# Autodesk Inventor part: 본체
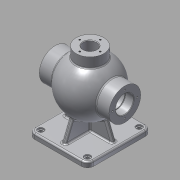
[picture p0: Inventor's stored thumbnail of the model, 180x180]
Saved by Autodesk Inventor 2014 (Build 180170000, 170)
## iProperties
Created: 2015-10
Part Number: 본체
Material: 알루미늄 6061
Document SubType Name: Modeling
Designer: youjin05
Density: 2.71 g/cm^3
Appearance: 알루미늄 - 평지
Mass: 1505.58 g
Surface Area: 1149.71 cm^2
Volume: 555.563 cm^3
Author: youjin05
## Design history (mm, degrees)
sketch "스케치1"
  geometry: L1 (-57.5, -62.5)-(57.5, -62.5); L2 (57.5, -62.5)-(57.5, 62.5); L3 (57.5, 62.5)-(-57.5, 62.5); L4 (-57.5, 62.5)-(-57.5, -62.5); L5 (-57.5, -62.5)-(57.5, 62.5); L6 (57.5, -62.5)-(-57.5, 62.5); 1 further point
  constraints: 12 end point, 2 midpoint, 2 parallel, 1 horizontal, 1 perpendicular
  dimensions: "d0" = 115 distance of L3.end L2.end; "d1" = 125 distance of L2.end L1.end
extrude "돌출1" new body sketch "스케치1" distance "d2" = 10; taper "d3" = 0 deg
sketch "스케치2"
  geometry: L1 (-57.5, 0)-(57.5, 0) reference; L2 (0, 32)-(0, 138); A1 r 53 centre (0, 85) between (0, 32) and (0, 138); 5 further points
  constraints: 3 midpoint, 3 point on circle, 3 vertical alignment, 2 end point, 1 centre point, 1 horizontal alignment, 1 perpendicular
  dimensions: "d6" = 53 radius of A1; "d7" = 85 distance of point (0, 0) A1.centre
revolve "회전1" sketch "스케치2" stored, may be unused: angle "d8" = 90 deg
node "작업 평면1"
sketch "스케치3"
  geometry: C1 r 53 at (0, 85) reference; C2 r 31 at (0, 85); 1 further point
  constraints: 1 centre point, 1 coincident
  dimensions: "d10" = 62 diameter of C2
extrude "돌출2" join sketch "스케치3" distance "d11" = 136; taper "d12" = 0 deg
node "작업 평면2"
sketch "스케치4"
  geometry: C1 r 27 at (0, 0); 1 further point
  constraints: 1 centre point, 1 coincident
  dimensions: "d14" = 54 diameter of C1
extrude "돌출3" join sketch "스케치4" stored distance "d15" = 136; taper "d16" = 0 deg
sketch "스케치5"
  geometry: L1 (-33.719, 44.109)-(-47.5, 10); L2 (-57.5, 0)-(57.5, 0) reference; L3 (57.5, 0)-(57.5, 10) reference; L4 (-57.5, 10)-(57.5, 10) reference; L5 (-57.5, 0)-(-57.5, 10) reference; L6 (-57.5, 10)-(57.5, 10) reference; L7 (-57.5, 0)-(-57.5, 10) reference; L8 (33.719, 44.109)-(47.5, 10); A1 r 53 centre (0, 85) between (-42.988, 54) and (-42.988, 116) reference; 1 further point
  constraints: 4 end point, 2 point on circle, 2 point on line
  dimensions: "d19" = 10 distance of L4.start L1.end; "d20" = 22 deg angle of L5 L1; "d93" = 22 deg angle of L8 L3; "d94" = 10 distance of L3.end L8.end
  node "투영된 루프1"
sketch "스케치6"
  geometry: L1 (-4, -4)-(4, -4); L2 (4, -4)-(4, 4); L3 (4, 4)-(-4, 4); L4 (-4, 4)-(-4, -4); L5 (-4, -4)-(4, 4); L6 (4, -4)-(-4, 4); 1 further point
  constraints: 12 end point, 2 midpoint, 2 parallel, 1 horizontal, 1 perpendicular
  dimensions: "d21" = 8 distance of L3.end L2.end; "d22" = 8 distance of L2.end L1.end
extrude "돌출4" join sketch "스케치6" stored distance "d23" = 136; taper "d24" = 0 deg
sketch "스케치7"
  geometry: L1 (62.5, 10)-(-62.5, 10) reference; L2 (-37.379, 47.426)-(-52.5, 10); L3 (37.379, 47.426)-(52.5, 10); L4 (62.5, 0)-(62.5, 10) reference; L5 (-62.5, 0)-(-62.5, 10) reference; A1 r 53 centre (0, 85) between (-27, 130.607) and (27, 130.607) reference; 1 further point
  constraints: 4 end point, 2 point on circle, 2 point on line
  dimensions: "d27" = 10 distance of L1.start L3.end; "d28" = 22 deg angle of L4 L3; "d29" = 10 distance of L1.end L2.end; "d30" = 22 deg angle of L5 L2
sketch "스케치8"
  geometry: C1 r 27 at (0, 0) reference; 5 further points
  dimensions: "d33" = 91 distance of point (-45.5, 50.5) point (45.5, 50.5); "d34" = 101 distance of point (45.5, 50.5) point (45.5, -50.5); "d35" = 45.5 horizontal distance of point (0, 0) point (45.5, 50.5); "d36" = 50.5 vertical distance of point (0, 0) point (45.5, 50.5); "d37" = 50.5 vertical distance of C1.centre point (-45.5, 50.5); "d38" = 50.5 vertical distance of point (-45.5, -50.5) point (0, 0); "d39" = 91 distance of point (45.5, -50.5) point (-45.5, -50.5); "d40" = 45.5 horizontal distance of point (0, 0) point (-45.5, -50.5)
hole "구멍1" sketch "스케치8" at (-45.5, 50.5), (45.5, 50.5), (45.5, -50.5), (-45.5, -50.5) diameter "d41" = 8; stored, may be unused: countersink angle "d45" = 90 deg, drill point angle "d47" = 118 deg; dims "d42" = 6, "d43" = 12, "d44" = 3, "d46" = 8
sketch "스케치9"
  geometry: L1 (0, 128)-(0, 42); A1 r 53 centre (0, 85) between (-42.988, 54) and (-42.988, 116) reference; A2 r 43 centre (0, 85) between (0, 42) and (0, 128); 2 further points
  constraints: 2 coincident, 2 end point, 2 point on circle, 1 centre point, 1 midpoint, 1 vertical
  dimensions: "d48" = 43 radius of A2
revolve "회전2" sketch "스케치9" stored, may be unused: angle "d49" = 90 deg
sketch "스케치10"
  geometry: C1 r 31 at (0, 0) reference; C2 r 17.5 at (0, 0); 1 further point
  constraints: 1 centre point, 1 coincident
  dimensions: "d50" = 35 diameter of C2
extrude "돌출7" cut sketch "스케치10" stored distance "d51" = 8; taper "d52" = 0 deg
sketch "스케치11"
  geometry: C1 r 27 at (0, 0) reference; C2 r 13 at (0, 0)
  constraints: 1 centre point, 1 coincident
  dimensions: "d53" = 26 diameter of C2
extrude "돌출8" cut sketch "스케치11" stored distance "d54" = 8; taper "d55" = 0 deg
sketch "스케치12"
  geometry: L1 (-50.25, 103.5)-(-50.25, 85); L2 (-68, 67.5)-(-68, 102.5) reference; L3 (-50.25, 103.5)-(-52, 103.5); L4 (-52, 103.5)-(-52, 85); L5 (-52, 85)-(-50.25, 85); 2 further points
  constraints: 8 end point, 3 perpendicular, 1 horizontal alignment, 1 midpoint, 1 vertical
  dimensions: "d57" = 18.5 distance of L1.start L1.end; "d58" = 1.75 distance of L1.start L3.end; "d122" = 16 distance between parallel lines of L2 L4
revolve "회전3" sketch "스케치12" stored, may be unused: angle "d59" = 90 deg
sketch "스케치13"
  geometry: C1 r 17.5 at (0, 0) reference; C2 r 31 at (0, 0) reference; A1 r 24 centre (0, 0) between (-24, 0) and (0, 24); 3 further points
  constraints: 4 point on circle, 2 horizontal alignment, 2 vertical alignment, 1 centre point, 1 coincident
  dimensions: "d60" = 48 diameter of A1
hole "구멍2" sketch "스케치13" at (-24, 0), (0, 24), (24, 0), (0, -24) diameter "d61" = 3.242; stored, may be unused: countersink angle "d65" = 90 deg, drill point angle "d67" = 118 deg; dims "d62" = 16, "d63" = 12, "d64" = 3, "d66" = 19
sketch "스케치14"
  geometry: C1 r 13 at (0, 0) reference; C2 r 27 at (0, 0) reference; A1 r 20 centre (0, 0) between (0, 20) and (20, 0); 2 further points
  constraints: 4 point on circle, 2 horizontal alignment, 2 vertical alignment, 1 centre point, 1 coincident
  dimensions: "d68" = 40 diameter of A1
hole "구멍3" sketch "스케치14" at (0, 20), (20, 0), (0, -20), (-20, 0) diameter "d69" = 3.242; stored, may be unused: countersink angle "d73" = 90 deg, drill point angle "d75" = 118 deg; dims "d70" = 9, "d71" = 12, "d72" = 3, "d74" = 11
sketch "스케치15"
  geometry: C1 r 17.5 at (0, 0) reference; C2 r 31 at (0, 0) reference; A1 r 22.5 centre (0, 0) between (22.5, 0) and (0, -22.5); 3 further points
  constraints: 4 point on circle, 2 horizontal alignment, 2 vertical alignment, 1 centre point, 1 coincident
  dimensions: "d76" = 45 diameter of A1
hole "구멍4" sketch "스케치15" at (22.5, 0), (0, 22.5), (-22.5, 0), (0, -22.5) diameter "d77" = 3.242; stored, may be unused: countersink angle "d81" = 90 deg, drill point angle "d83" = 118 deg; dims "d78" = 12, "d79" = 12, "d80" = 3, "d82" = 15
chamfer "모따기1" distance "d84" = 1; stored, may be unused: second distance "d85" = 2, angle "d86" = 45 deg
fillet "모깎기1" dims "d87" = 3
fillet "모깎기2" dims "d88" = 12
fillet "모깎기3" dims "d89" = 3
feature "리브1" dims "d95" = 1, "d96" = 8, "d97" = 0, "d98" = 0, "d99" = 1, "d100" = 1
feature "리브2" dims "d101" = 1, "d102" = 8, "d103" = 0, "d104" = 0, "d105" = 1, "d106" = 1
node "작업 평면3"
node "작업 평면4"
sketch "스케치17" dims "d10" = 62
  geometry: L1 (-27, 0)-(27, 0) reference; 2 further points
  constraints: 1 vertical alignment, 1 other
  dimensions: "d115" = 10 distance from line of L1 point (0, -10)
feature "엠보싱2" sketch "스케치17" dims "d116" = 0.5, "d117" = 0
sketch "스케치18"
  geometry: L1 (-45.5, 10)-(45.5, 10) reference; L2 (39.5, 10)-(51.5, 10) reference; L3 (33.719, 44.109)-(47.5, 10); L4 (57.5, 7)-(57.5, 0) reference; A1 r 53 centre (0, 85) between (-42.113, 52.821) and (-42.113, 117.179) reference; A2 r 54.948 centre (54.5, 7) between (0, 0) and (0, 0) reference; 1 further point
  constraints: 2 end point, 1 point on circle, 1 point on line
  dimensions: "d118" = 10 distance from line of L4 L3.end; "d119" = 22 deg angle of L4 L3
fillet "모깎기9" dims "d120" = 3
fillet "모깎기10" dims "d121" = 3
node "솔리드1"
mirror "대칭1"
mirror "대칭2"
other parameters: "d9" = -68
